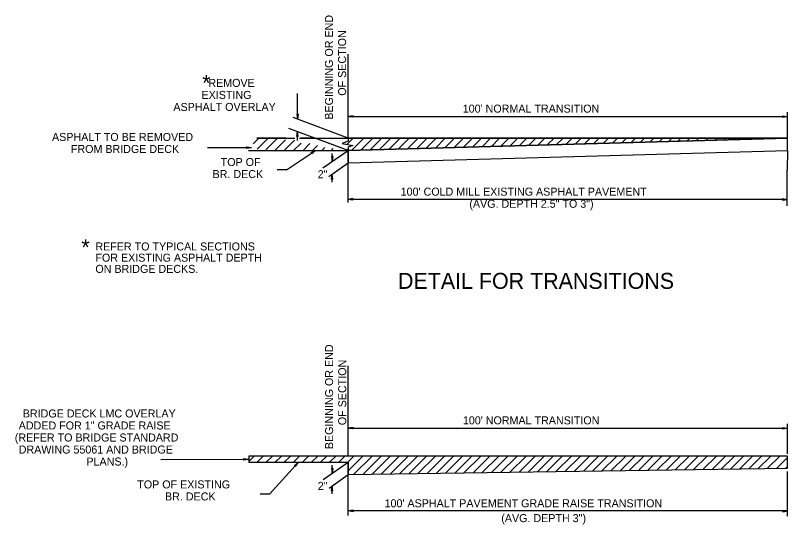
# Model space of a CAD drawing. Extents: x 1926836 to 1933254, y 596317 to 604524.
# Drawn here: x 1928675 to 1929254, y 600453 to 600834 of the extents above; entities that cross this region are included whole.
import ezdxf

# ---------------------------------------------------------------- set-up
doc = ezdxf.new("R2010")
doc.units = 0
doc.layers.add('Default', color=7, linetype='Continuous')
doc.layers.add('R_Annotation', color=7, linetype='Continuous')

msp = doc.modelspace()

# ---------------------------------------------------------------- linework, layer by layer
at = {"layer": 'Default'}
for p, q in [((1928924.46, 600742.66), (1928924.46, 600805.24)), ((1928886.56, 600756.59), (1928886.56, 600775.78)), ((1929253.71, 600742.24), (1929253.71, 600761.61)), ((1928924.46, 600742.24), (1928883.18, 600757.66)), ((1928886.02, 600760.15), (1928886.56, 600756.59)), ((1928886.02, 600760.15), (1928886.56, 600757.12)), ((1928887.09, 600760.15), (1928886.02, 600760.15)), ((1928886.21, 600760.15), (1928886.56, 600757.84)), ((1928886.21, 600760.15), (1928886.56, 600758.36)), ((1928886.38, 600760.15), (1928886.56, 600759.08)), ((1928886.38, 600760.15), (1928886.56, 600759.6)), ((1928887.09, 600760.15), (1928886.56, 600756.59)), ((1928886.73, 600760.15), (1928886.56, 600759.08)), ((1928886.91, 600760.15), (1928886.56, 600757.84)), ((1928886.91, 600760.15), (1928886.56, 600757.12)), ((1928886.73, 600760.15), (1928886.56, 600758.36)), ((1928886.56, 600760.15), (1928886.56, 600759.6)), ((1928928.2, 600758.95), (1928924.46, 600758.42)), ((1928924.46, 600758.42), (1929253.71, 600758.42)), ((1928928.2, 600757.89), (1928924.46, 600758.42)), ((1928928.2, 600758.77), (1928925.01, 600758.42)), ((1928928.2, 600757.89), (1928925.01, 600758.42)), ((1928928.2, 600758.77), (1928925.71, 600758.42)), ((1928928.2, 600758.06), (1928925.71, 600758.42)), ((1928928.2, 600758.59), (1928926.43, 600758.42)), ((1928928.2, 600758.06), (1928926.43, 600758.42)), ((1928928.2, 600758.59), (1928926.96, 600758.42)), ((1928928.2, 600758.24), (1928926.96, 600758.42)), ((1928928.2, 600758.42), (1928927.67, 600758.42)), ((1928928.2, 600758.24), (1928927.67, 600758.42)), ((1928928.2, 600757.89), (1928928.2, 600758.95)), ((1929249.97, 600758.95), (1929253.71, 600758.42)), ((1929249.97, 600758.95), (1929249.97, 600757.89)), ((1929249.97, 600758.77), (1929252.47, 600758.42)), ((1929249.97, 600758.77), (1929252.99, 600758.42)), ((1929249.97, 600758.59), (1929251.21, 600758.42)), ((1929249.97, 600758.59), (1929251.76, 600758.42)), ((1929249.97, 600757.89), (1929253.71, 600758.42)), ((1929249.97, 600758.24), (1929251.21, 600758.42)), ((1929249.97, 600758.06), (1929252.47, 600758.42)), ((1929249.97, 600757.89), (1929252.99, 600758.42)), ((1929249.97, 600758.06), (1929251.76, 600758.42)), ((1929249.97, 600758.24), (1929250.51, 600758.42)), ((1929249.97, 600758.42), (1929250.51, 600758.42)), ((1928924.46, 600733.01), (1928880.16, 600749.55)), ((1928886.02, 600743.42), (1928886.56, 600747.15)), ((1928886.02, 600743.42), (1928886.56, 600746.62)), ((1928886.02, 600743.42), (1928887.09, 600743.42)), ((1928886.21, 600743.42), (1928886.56, 600745.91)), ((1928886.21, 600743.42), (1928886.56, 600745.38)), ((1928886.38, 600743.42), (1928886.56, 600744.67)), ((1928886.38, 600743.42), (1928886.56, 600743.95)), ((1928887.09, 600743.42), (1928886.56, 600747.15)), ((1928886.56, 600740.4), (1928886.56, 600747.15)), ((1928886.91, 600743.42), (1928886.56, 600746.62)), ((1928886.91, 600743.42), (1928886.56, 600745.91)), ((1928886.73, 600743.42), (1928886.56, 600745.38)), ((1928886.73, 600743.42), (1928886.56, 600744.67)), ((1928886.56, 600743.42), (1928886.56, 600743.95)), ((1928853.25, 600738.01), (1928857.48, 600742.24)), ((1928856.1, 600742.24), (1928884.65, 600742.24)), ((1928856.41, 600734.1), (1928864.55, 600742.24)), ((1928862.83, 600733.45), (1928871.62, 600742.24)), ((1928869.46, 600733.01), (1928877.46, 600741.02)), ((1928876.53, 600733.01), (1928884.26, 600740.74)), ((1928883.6, 600733.01), (1928889.2, 600738.61)), ((1928888.01, 600742.24), (1929253.71, 600742.24)), ((1928890.67, 600733.01), (1928895.86, 600738.19)), ((1928923.64, 600737.7), (1928928.19, 600742.24)), ((1928924.46, 600733.01), (1929253.71, 600742.24)), ((1928934.01, 600733.28), (1928942.97, 600742.24)), ((1929253.71, 600733.01), (1929253.71, 600742.24)), ((1928819.01, 600735.19), (1928852.17, 600735.31)), ((1928848.4, 600734.74), (1928848.44, 600735.86)), ((1928848.4, 600735.62), (1928850.89, 600735.26)), ((1928848.4, 600734.74), (1928852.17, 600735.31)), ((1928848.44, 600735.86), (1928852.17, 600735.31)), ((1928848.44, 600734.98), (1928849.76, 600735.29)), ((1928848.44, 600734.98), (1928850.24, 600735.22)), ((1928848.48, 600735.23), (1928849.11, 600735.26)), ((1928848.48, 600735.23), (1928849.11, 600735.26)), ((1928848.52, 600735.47), (1928849.76, 600735.29)), ((1928848.52, 600735.47), (1928850.24, 600735.22)), ((1928848.54, 600735.72), (1928851.53, 600735.29)), ((1928848.55, 600734.84), (1928851.53, 600735.29)), ((1928848.55, 600734.84), (1928850.89, 600735.26)), ((1928849.86, 600733.01), (1928924.46, 600733.01)), ((1928878.32, 600718.52), (1928900.09, 600733.01)), ((1928896.67, 600731.41), (1928900.09, 600733.01)), ((1928897.26, 600730.45), (1928896.67, 600731.41)), ((1928896.78, 600731.19), (1928899.05, 600732.26)), ((1928896.83, 600731.36), (1928899.57, 600732.64)), ((1928896.95, 600731.13), (1928898.53, 600731.87)), ((1928896.95, 600731.13), (1928898.09, 600731.66)), ((1928897.16, 600730.68), (1928898.53, 600731.87)), ((1928897.16, 600730.68), (1928898.09, 600731.66)), ((1928897.26, 600730.45), (1928900.09, 600733.01)), ((1928897.32, 600730.62), (1928899.57, 600732.64)), ((1928897.32, 600730.62), (1928899.05, 600732.26)), ((1928897.74, 600733.01), (1928901.58, 600736.85)), ((1928904.81, 600733.01), (1928907.01, 600735.21)), ((1928905.62, 600719.97), (1928924.46, 600733.01)), ((1928911.89, 600733.01), (1928913.28, 600734.41)), ((1928918.96, 600733.01), (1928919.25, 600733.3)), ((1928924.46, 600694.16), (1928924.46, 600734.38)), ((1928924.47, 600723.78), (1929253.71, 600733.01)), ((1929253.71, 600733.01), (1929253.53, 600718.35)), ((1928897.06, 600730.91), (1928897.56, 600731.28)), ((1928897.06, 600730.91), (1928897.56, 600731.28)), ((1928911.98, 600728.44), (1928912.5, 600724.71)), ((1928913.04, 600728.44), (1928911.98, 600728.44)), ((1928912.16, 600728.44), (1928912.5, 600725.95)), ((1928912.16, 600728.44), (1928912.5, 600725.42)), ((1928912.32, 600728.44), (1928912.5, 600727.2)), ((1928912.32, 600728.44), (1928912.5, 600726.67)), ((1928912.5, 600724.71), (1928912.5, 600730.77)), ((1928913.04, 600728.44), (1928912.5, 600724.71)), ((1928912.68, 600728.44), (1928912.5, 600727.2)), ((1928912.87, 600728.44), (1928912.5, 600725.95)), ((1928913.04, 600728.44), (1928912.5, 600725.42)), ((1928912.87, 600728.44), (1928912.5, 600726.67)), ((1928912.5, 600728.44), (1928912.5, 600727.91)), ((1928912.68, 600728.44), (1928912.5, 600727.91)), ((1928910.08, 600713.64), (1928924.47, 600723.78)), ((1928878.32, 600718.52), (1928871.31, 600718.52)), ((1928911.96, 600711.54), (1928912.49, 600715.28)), ((1928912.14, 600711.54), (1928912.49, 600714.74)), ((1928912.14, 600711.54), (1928912.49, 600714.02)), ((1928913.03, 600711.54), (1928912.49, 600715.28)), ((1928912.49, 600709.23), (1928912.49, 600715.28)), ((1928913.03, 600711.54), (1928912.49, 600714.74)), ((1928912.85, 600711.54), (1928912.49, 600714.02)), ((1929253.53, 600691.56), (1929253.53, 600718.35)), ((1928911.96, 600711.54), (1928913.03, 600711.54)), ((1928912.31, 600711.54), (1928912.49, 600713.49)), ((1928912.31, 600711.54), (1928912.49, 600712.78)), ((1928912.85, 600711.54), (1928912.49, 600713.49)), ((1928912.67, 600711.54), (1928912.49, 600712.78)), ((1928912.67, 600711.54), (1928912.49, 600712.26)), ((1928912.49, 600711.54), (1928912.49, 600712.26)), ((1928928.03, 600696.94), (1928924.46, 600696.41)), ((1928928.03, 600696.94), (1928925.01, 600696.41)), ((1928928.03, 600696.77), (1928925.71, 600696.41)), ((1928928.03, 600696.77), (1928926.25, 600696.41)), ((1928928.03, 600695.87), (1928928.03, 600696.94)), ((1929249.97, 600696.94), (1929253.53, 600696.41)), ((1929249.97, 600696.94), (1929252.99, 600696.41)), ((1929249.97, 600696.94), (1929249.97, 600695.87)), ((1929249.97, 600696.77), (1929252.28, 600696.41)), ((1929249.97, 600696.77), (1929251.76, 600696.41)), ((1929253.53, 600696.41), (1928924.46, 600696.41)), ((1928928.03, 600695.87), (1928924.46, 600696.41)), ((1928928.03, 600696.05), (1928925.01, 600696.41)), ((1928928.03, 600696.05), (1928925.71, 600696.41)), ((1928928.03, 600696.23), (1928926.25, 600696.41)), ((1928928.03, 600696.58), (1928926.96, 600696.41)), ((1928928.03, 600696.23), (1928926.96, 600696.41)), ((1928928.03, 600696.58), (1928927.49, 600696.41)), ((1928928.03, 600696.41), (1928927.49, 600696.41)), ((1929249.97, 600696.58), (1929251.05, 600696.41)), ((1929249.97, 600696.58), (1929250.51, 600696.41)), ((1929249.97, 600695.87), (1929253.53, 600696.41)), ((1929249.97, 600696.23), (1929251.05, 600696.41)), ((1929249.97, 600696.05), (1929252.28, 600696.41)), ((1929249.97, 600696.05), (1929252.99, 600696.41)), ((1929249.97, 600696.23), (1929251.76, 600696.41)), ((1929249.97, 600696.41), (1929250.51, 600696.41)), ((1928924.56, 600504.15), (1928924.56, 600571.77)), ((1928928.29, 600525.48), (1928924.56, 600524.95)), ((1928924.56, 600524.95), (1929253.62, 600524.95)), ((1928928.29, 600524.42), (1928924.56, 600524.95)), ((1928928.29, 600525.31), (1928925.1, 600524.95)), ((1928928.29, 600524.42), (1928925.1, 600524.95)), ((1928928.29, 600525.31), (1928925.81, 600524.95)), ((1928928.29, 600524.59), (1928925.81, 600524.95)), ((1928928.29, 600525.12), (1928926.52, 600524.95)), ((1928928.29, 600524.59), (1928926.52, 600524.95)), ((1928928.29, 600525.12), (1928927.05, 600524.95)), ((1928928.29, 600524.77), (1928927.05, 600524.95)), ((1928928.29, 600524.95), (1928927.76, 600524.95)), ((1928928.29, 600524.77), (1928927.76, 600524.95)), ((1928928.29, 600524.42), (1928928.29, 600525.48)), ((1929249.88, 600525.48), (1929253.62, 600524.95)), ((1929249.88, 600525.48), (1929249.88, 600524.42)), ((1929249.88, 600525.31), (1929252.37, 600524.95)), ((1929249.88, 600525.31), (1929252.89, 600524.95)), ((1929249.88, 600525.12), (1929251.12, 600524.95)), ((1929249.88, 600525.12), (1929251.67, 600524.95)), ((1929249.88, 600524.42), (1929253.62, 600524.95)), ((1929249.88, 600524.77), (1929251.12, 600524.95)), ((1929249.88, 600524.59), (1929252.37, 600524.95)), ((1929249.88, 600524.42), (1929252.89, 600524.95)), ((1929249.88, 600524.59), (1929251.67, 600524.95)), ((1929249.88, 600524.77), (1929250.42, 600524.95)), ((1929249.88, 600524.95), (1929250.42, 600524.95)), ((1929253.62, 600505.87), (1929253.62, 600528.27)), ((1928784.25, 600501.6), (1928849.96, 600501.84)), ((1928846.19, 600501.27), (1928846.23, 600502.39)), ((1928846.19, 600502.15), (1928848.68, 600501.79)), ((1928846.19, 600501.27), (1928849.96, 600501.84)), ((1928846.23, 600502.39), (1928849.96, 600501.84)), ((1928846.23, 600501.51), (1928847.55, 600501.82)), ((1928846.23, 600501.51), (1928848.03, 600501.75)), ((1928846.27, 600501.76), (1928846.9, 600501.79)), ((1928846.27, 600501.76), (1928846.9, 600501.79)), ((1928846.3, 600502), (1928847.55, 600501.82)), ((1928846.3, 600502), (1928848.03, 600501.75)), ((1928846.33, 600502.25), (1928849.32, 600501.82)), ((1928846.33, 600501.37), (1928849.32, 600501.82)), ((1928846.33, 600501.37), (1928848.68, 600501.79)), ((1928849.96, 600499.54), (1928924.56, 600499.54)), ((1928865.49, 600475.7), (1928887.26, 600499.54)), ((1928884.33, 600497.17), (1928887.26, 600499.54)), ((1928885.13, 600496.37), (1928884.33, 600497.17)), ((1928884.48, 600496.98), (1928886.43, 600498.56)), ((1928884.5, 600497.15), (1928886.85, 600499.05)), ((1928884.66, 600496.96), (1928886.02, 600498.06)), ((1928884.66, 600496.96), (1928885.64, 600497.75)), ((1928884.82, 600496.77), (1928885.22, 600497.25)), ((1928884.82, 600496.77), (1928885.22, 600497.25)), ((1928884.98, 600496.57), (1928886.02, 600498.06)), ((1928884.98, 600496.57), (1928885.64, 600497.75)), ((1928885.13, 600496.37), (1928887.26, 600499.54)), ((1928885.15, 600496.55), (1928886.85, 600499.05)), ((1928885.15, 600496.55), (1928886.43, 600498.56)), ((1928905.71, 600486.5), (1928924.56, 600499.54)), ((1928912.07, 600494.97), (1928912.6, 600491.24)), ((1928913.13, 600494.97), (1928912.07, 600494.97)), ((1928912.25, 600494.97), (1928912.6, 600492.49)), ((1928912.25, 600494.97), (1928912.6, 600491.95)), ((1928912.42, 600494.97), (1928912.6, 600493.73)), ((1928912.42, 600494.97), (1928912.6, 600493.2)), ((1928912.6, 600491.24), (1928912.6, 600497.3)), ((1928913.13, 600494.97), (1928912.6, 600491.24)), ((1928912.78, 600494.97), (1928912.6, 600493.73)), ((1928912.96, 600494.97), (1928912.6, 600492.49)), ((1928913.13, 600494.97), (1928912.6, 600491.95)), ((1928912.96, 600494.97), (1928912.6, 600493.2)), ((1928912.6, 600494.97), (1928912.6, 600494.44)), ((1928912.78, 600494.97), (1928912.6, 600494.44)), ((1928924.56, 600459.65), (1928924.56, 600499.54)), ((1928910.17, 600480.17), (1928924.56, 600490.31)), ((1929253.62, 600459.16), (1929253.62, 600492.56)), ((1928912.06, 600478.07), (1928912.58, 600481.81)), ((1928912.06, 600478.07), (1928913.12, 600478.07)), ((1928912.24, 600478.07), (1928912.58, 600481.27)), ((1928912.24, 600478.07), (1928912.58, 600480.55)), ((1928912.4, 600478.07), (1928912.58, 600480.02)), ((1928912.4, 600478.07), (1928912.58, 600479.31)), ((1928913.12, 600478.07), (1928912.58, 600481.81)), ((1928912.58, 600475.76), (1928912.58, 600481.81)), ((1928913.12, 600478.07), (1928912.58, 600481.27)), ((1928912.95, 600478.07), (1928912.58, 600480.55)), ((1928912.95, 600478.07), (1928912.58, 600480.02)), ((1928912.76, 600478.07), (1928912.58, 600479.31)), ((1928912.76, 600478.07), (1928912.58, 600478.79)), ((1928912.58, 600478.07), (1928912.58, 600478.79)), ((1928865.49, 600475.7), (1928858.47, 600475.7)), ((1928928.13, 600463.53), (1928924.56, 600463.01)), ((1929253.62, 600463.01), (1928924.56, 600463.01)), ((1928928.13, 600462.47), (1928924.56, 600463.01)), ((1928928.13, 600463.53), (1928925.1, 600463.01)), ((1928928.13, 600462.65), (1928925.1, 600463.01)), ((1928928.13, 600463.37), (1928925.81, 600463.01)), ((1928928.13, 600462.65), (1928925.81, 600463.01)), ((1928928.13, 600463.37), (1928926.34, 600463.01)), ((1928928.13, 600462.83), (1928926.34, 600463.01)), ((1928928.13, 600463.18), (1928927.05, 600463.01)), ((1928928.13, 600462.83), (1928927.05, 600463.01)), ((1928928.13, 600463.18), (1928927.59, 600463.01)), ((1928928.13, 600463.01), (1928927.59, 600463.01)), ((1928928.13, 600462.47), (1928928.13, 600463.53)), ((1929250.06, 600463.53), (1929253.62, 600463.01)), ((1929250.06, 600463.53), (1929253.08, 600463.01)), ((1929250.06, 600463.53), (1929250.06, 600462.47)), ((1929250.06, 600463.37), (1929252.37, 600463.01)), ((1929250.06, 600463.37), (1929251.85, 600463.01)), ((1929250.06, 600463.18), (1929251.14, 600463.01)), ((1929250.06, 600463.18), (1929250.6, 600463.01)), ((1929250.06, 600462.47), (1929253.62, 600463.01)), ((1929250.06, 600462.83), (1929251.14, 600463.01)), ((1929250.06, 600462.65), (1929252.37, 600463.01)), ((1929250.06, 600462.65), (1929253.08, 600463.01)), ((1929250.06, 600462.83), (1929251.85, 600463.01)), ((1929250.06, 600463.01), (1929250.6, 600463.01))]:
    msp.add_line(p, q, dxfattribs=at)
for points in [[(1928877.92, 600742.24), (1928856.1, 600742.24)], [(1928924.46, 600733.01), (1928899.74, 600742.24), (1928888.83, 600742.24)], [(1928924.46, 600740.05), (1928919.93, 600738.32), (1928928.12, 600736.8), (1928924.47, 600735.45)], [(1928924.46, 600733.01), (1928924.47, 600723.78), (1929253.71, 600733.01), (1929253.71, 600742.24), (1928924.46, 600733.01)], [(1928924.46, 600733.01), (1928924.47, 600723.78), (1929253.71, 600733.01), (1929253.71, 600742.24), (1928924.46, 600733.01)], [(1928924.46, 600733.01), (1928924.47, 600723.78), (1929253.71, 600733.01), (1929253.71, 600742.24), (1928924.46, 600733.01)], [(1928924.56, 600499.54), (1928924.56, 600499.54)]]:
    msp.add_lwpolyline(points, dxfattribs=at)
at = {"layer": 'R_Annotation'}
for p, q in [((1928927.03, 600733.08), (1928936.19, 600742.24)), ((1928941, 600733.48), (1928949.76, 600742.24)), ((1928947.98, 600733.67), (1928956.55, 600742.24)), ((1928954.96, 600733.87), (1928963.34, 600742.24)), ((1928961.95, 600734.06), (1928970.13, 600742.24)), ((1928968.93, 600734.26), (1928976.91, 600742.24)), ((1928975.92, 600734.45), (1928983.7, 600742.24)), ((1928982.9, 600734.65), (1928990.49, 600742.24)), ((1928989.88, 600734.85), (1928997.28, 600742.24)), ((1928996.87, 600735.04), (1929004.07, 600742.24)), ((1929003.85, 600735.24), (1929010.86, 600742.24)), ((1929010.84, 600735.43), (1929017.64, 600742.24)), ((1929017.82, 600735.63), (1929024.43, 600742.24)), ((1929024.8, 600735.82), (1929031.22, 600742.24)), ((1929031.79, 600736.02), (1929038.01, 600742.24)), ((1929038.77, 600736.22), (1929044.8, 600742.24)), ((1929045.76, 600736.41), (1929051.58, 600742.24)), ((1929052.74, 600736.61), (1929058.37, 600742.24)), ((1929059.72, 600736.8), (1929065.16, 600742.24)), ((1929066.71, 600737), (1929071.95, 600742.24)), ((1929073.69, 600737.19), (1929078.74, 600742.24)), ((1929080.68, 600737.39), (1929085.53, 600742.24)), ((1929087.66, 600737.59), (1929092.31, 600742.24)), ((1929094.64, 600737.78), (1929099.1, 600742.24)), ((1929101.63, 600737.98), (1929105.89, 600742.24)), ((1929108.61, 600738.17), (1929112.68, 600742.24)), ((1929115.6, 600738.37), (1929119.47, 600742.24)), ((1929122.58, 600738.56), (1929126.26, 600742.24)), ((1929129.56, 600738.76), (1929133.04, 600742.24)), ((1929136.55, 600738.96), (1929139.83, 600742.24)), ((1929143.53, 600739.15), (1929146.62, 600742.24)), ((1929150.52, 600739.35), (1929153.41, 600742.24)), ((1929157.5, 600739.54), (1929160.2, 600742.24)), ((1929164.48, 600739.74), (1929166.98, 600742.24)), ((1929171.47, 600739.94), (1929173.77, 600742.24)), ((1929178.45, 600740.13), (1929180.56, 600742.24)), ((1929185.44, 600740.33), (1929187.35, 600742.24)), ((1929192.42, 600740.52), (1929194.14, 600742.24)), ((1929199.4, 600740.72), (1929200.93, 600742.24)), ((1929206.39, 600740.91), (1929207.71, 600742.24)), ((1929213.37, 600741.11), (1929214.5, 600742.24)), ((1929220.36, 600741.31), (1929221.29, 600742.24)), ((1929227.34, 600741.5), (1929228.08, 600742.24)), ((1929234.32, 600741.7), (1929234.87, 600742.24)), ((1929241.31, 600741.89), (1929241.66, 600742.24)), ((1929248.29, 600742.09), (1929248.44, 600742.24)), ((1928913.47, 600504.16), (1928849.96, 600504.15)), ((1928849.96, 600504.15), (1928849.96, 600499.54)), ((1928849.96, 600499.97), (1928854.14, 600504.15)), ((1928856.31, 600499.54), (1928860.92, 600504.15)), ((1928863.1, 600499.54), (1928867.71, 600504.15)), ((1928869.89, 600499.54), (1928874.5, 600504.15)), ((1928876.67, 600499.54), (1928881.29, 600504.15)), ((1928883.46, 600499.54), (1928888.08, 600504.16)), ((1928890.25, 600499.54), (1928894.87, 600504.16)), ((1928897.04, 600499.54), (1928901.66, 600504.16)), ((1928903.83, 600499.54), (1928908.45, 600504.16)), ((1928910.62, 600499.54), (1928915.23, 600504.16)), ((1928924.56, 600504.15), (1928913.47, 600504.16)), ((1928917.41, 600499.54), (1928922.02, 600504.16)), ((1928924.2, 600499.54), (1928928.81, 600504.15)), ((1929253.62, 600504.19), (1928924.56, 600504.15)), ((1929253.62, 600504.19), (1928924.56, 600504.15)), ((1928924.56, 600493.12), (1928935.6, 600504.16)), ((1928928.59, 600490.36), (1928942.39, 600504.16)), ((1928935.48, 600490.46), (1928949.18, 600504.16)), ((1928942.37, 600490.56), (1928955.96, 600504.16)), ((1928949.25, 600490.66), (1928962.75, 600504.16)), ((1928956.14, 600490.75), (1928969.54, 600504.16)), ((1928963.02, 600490.85), (1928976.33, 600504.16)), ((1928969.91, 600490.95), (1928983.12, 600504.16)), ((1928976.79, 600491.04), (1928989.91, 600504.16)), ((1928983.68, 600491.14), (1928996.7, 600504.16)), ((1928990.56, 600491.24), (1929003.49, 600504.16)), ((1928997.45, 600491.34), (1929010.28, 600504.16)), ((1929004.33, 600491.43), (1929017.06, 600504.16)), ((1929011.22, 600491.53), (1929023.85, 600504.16)), ((1929018.11, 600491.63), (1929030.64, 600504.17)), ((1929024.99, 600491.73), (1929037.43, 600504.17)), ((1929031.88, 600491.82), (1929044.22, 600504.17)), ((1929038.76, 600491.92), (1929051.01, 600504.17)), ((1929045.65, 600492.02), (1929057.8, 600504.17)), ((1929052.53, 600492.11), (1929064.59, 600504.17)), ((1929059.42, 600492.21), (1929071.38, 600504.17)), ((1929066.3, 600492.31), (1929078.16, 600504.17)), ((1929073.19, 600492.41), (1929084.95, 600504.17)), ((1929080.07, 600492.5), (1929091.74, 600504.17)), ((1929086.96, 600492.6), (1929098.53, 600504.17)), ((1929093.85, 600492.7), (1929105.32, 600504.17)), ((1929100.73, 600492.8), (1929112.11, 600504.17)), ((1929107.62, 600492.89), (1929118.9, 600504.17)), ((1929114.5, 600492.99), (1929125.69, 600504.17)), ((1929121.39, 600493.09), (1929132.48, 600504.18)), ((1929128.27, 600493.18), (1929139.27, 600504.18)), ((1929135.16, 600493.28), (1929146.05, 600504.18)), ((1929142.04, 600493.38), (1929152.84, 600504.18)), ((1929148.93, 600493.48), (1929159.63, 600504.18)), ((1929155.82, 600493.57), (1929166.42, 600504.18)), ((1929162.7, 600493.67), (1929173.21, 600504.18)), ((1929169.59, 600493.77), (1929180, 600504.18)), ((1929176.47, 600493.87), (1929186.79, 600504.18)), ((1929183.36, 600493.96), (1929193.58, 600504.18)), ((1929190.24, 600494.06), (1929200.37, 600504.18)), ((1929197.13, 600494.16), (1929207.15, 600504.18)), ((1929204.01, 600494.25), (1929213.94, 600504.18)), ((1929210.9, 600494.35), (1929220.73, 600504.18)), ((1929217.78, 600494.45), (1929227.52, 600504.19)), ((1929224.67, 600494.55), (1929234.31, 600504.19)), ((1929231.56, 600494.64), (1929241.1, 600504.19)), ((1929238.44, 600494.74), (1929247.89, 600504.19)), ((1929245.33, 600494.84), (1929253.62, 600503.13)), ((1929253.63, 600494.96), (1929253.62, 600504.19)), ((1929253.63, 600494.96), (1929253.62, 600504.19)), ((1929253.63, 600494.96), (1929253.62, 600504.19)), ((1928924.56, 600499.54), (1928924.55, 600490.31)), ((1928924.55, 600490.31), (1929253.63, 600494.96)), ((1928924.55, 600490.31), (1929253.63, 600494.96)), ((1929252.21, 600494.94), (1929253.63, 600496.35))]:
    msp.add_line(p, q, dxfattribs=at)
for points in [[(1928924.46, 600735.45), (1928924.46, 600733.01), (1929253.71, 600742.24), (1928924.46, 600742.24)], [(1928924.46, 600742.24), (1928924.46, 600740.05)], [(1928849.96, 600499.54), (1928924.56, 600499.54)]]:
    msp.add_lwpolyline(points, dxfattribs=at)

# ---------------------------------------------------------------- texts
at = {"layer": 'Default'}
for s, height, rotation, p in [('BEGINNING OR END', 6, 90, (1928913.11, 600756.08)), ('OF SECTION', 6, 90, (1928922.97, 600774.02)), (' REMOVE', 6, 360, (1928817.51, 600780.63)), ('EXISTING ', 6, 360, (1928814.64, 600771.63)), ('ASPHALT OVERLAY', 6, 360, (1928793.54, 600762.63)), ("100' NORMAL TRANSITION ", 6, 360, (1929010.34, 600761.37)), ('ASPHALT TO BE REMOVED', 6, 360, (1928702.63, 600740.15)), (' FROM BRIDGE DECK', 6, 360, (1928714.51, 600731.15)), ('TOP OF ', 6, 360, (1928828.99, 600721.36)), ('BR. DECK', 6, 360, (1928822.89, 600712.36)), ('2"', 6, 360, (1928901.65, 600712.26)), ("100' COLD MILL EXISTING ASPHALT PAVEMENT", 6, 360, (1928963.84, 600699.18)), ('(AVG. DEPTH 2.5" TO 3")', 6, 360, (1929015.31, 600690.11)), ('DETAIL FOR TRANSITIONS', 12, 360, (1928961.83, 600629.38)), ('BEGINNING OR END', 6, 90, (1928913.2, 600509.33)), ('OF SECTION', 6, 90, (1928923.06, 600527.27)), ('BRIDGE DECK LMC OVERLAY ', 6, 360, (1928680.7, 600533.05)), ('ADDED FOR 1" GRADE RAISE', 6, 360, (1928677.67, 600524.05)), ("100' NORMAL TRANSITION ", 6, 360, (1929010.44, 600527.9)), ('(REFER TO BRIDGE STANDARD', 6, 360, (1928674.71, 600515.05)), ('DRAWING 55061 AND BRIDGE', 6, 360, (1928677.67, 600506.05)), (' PLANS.)', 6, 360, (1928726.15, 600497.05)), ('TOP OF EXISTING ', 6, 360, (1928766.48, 600479.92)), ('2"', 6, 360, (1928901.74, 600478.79)), ('BR. DECK', 6, 360, (1928787.27, 600470.92)), ("100' ASPHALT PAVEMENT GRADE RAISE TRANSITION", 6, 360, (1928951.78, 600465.78)), ('(AVG. DEPTH 3")', 6, 360, (1929039.22, 600454.66))]:
    msp.add_text(s, height=height, rotation=rotation, dxfattribs=at).set_placement(p)
at = {"layer": 'R_Annotation'}
for s, height, p in [('*', 12, (1928815.12, 600777.66)), ('*', 12, (1928724.63, 600654.59)), ('REFER TO TYPICAL SECTIONS', 6, (1928735.11, 600658.14)), ('FOR EXISTING ASPHALT DEPTH ', 6, (1928735.11, 600649.74)), ('ON BRIDGE DECKS.', 6, (1928735.11, 600641.34))]:
    msp.add_text(s, height=height, rotation=360, dxfattribs=at).set_placement(p)

doc.saveas('drawing.dxf')
